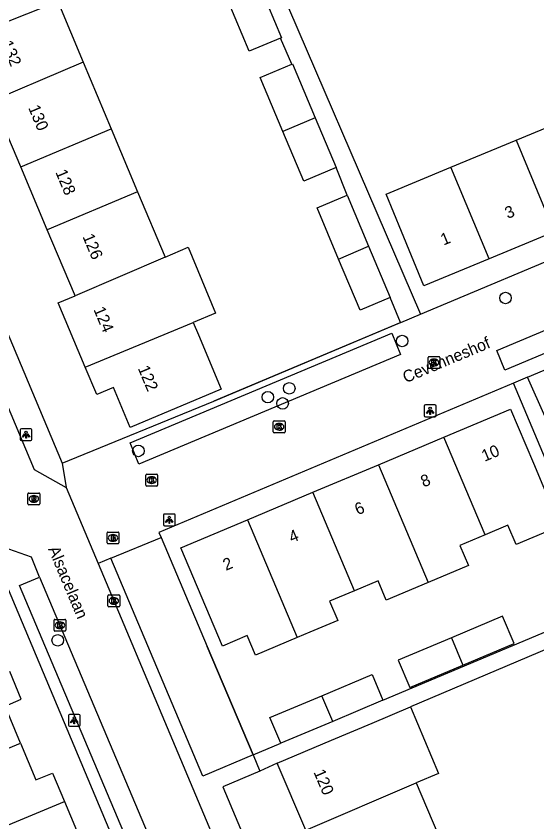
# Model space of a CAD drawing. Extents: x 157767 to 159171, y 387842 to 389425.
# Drawn here: x 158840.3 to 158884.5, y 388397.2 to 388465.6 of the extents above; entities that cross this region are included whole.
import ezdxf

# ---------------------------------------------------------------- set-up
doc = ezdxf.new("R2010")
doc.units = 0
for name, color, linetype in [('IMGEO_Boom', 7, 'Continuous'), ('IMGEO_Brandkraan', 7, 'Continuous'), ('IMGEO_Kolk', 7, 'Continuous'), ('IMGEO_Lichtpunt', 7, 'Continuous'), ('IMGEO_Muur', 7, 'Continuous'), ('IMGEO_Openbare_ruimte_label', 7, 'Continuous'), ('IMGEO_Pand', 7, 'Continuous'), ('IMGEO_Pand_nummerreeks', 7, 'Continuous'), ('IMGEO_Parkeervlak_open', 7, 'Continuous'), ('IMGEO_Rijbaan_lokaal_open', 7, 'Continuous'), ('IMGEO_Rioolput', 7, 'Continuous'), ('IMGEO_Voetpad_open', 7, 'Continuous')]:
    doc.layers.add(name, color=color, linetype=linetype)

msp = doc.modelspace()

# ---------------------------------------------------------------- linework, layer by layer
at = {"layer": 'IMGEO_Boom'}
for centre in [(158881.81, 388441.636), (158873.055, 388437.985), (158863.477, 388433.968), (158861.666, 388433.215), (158862.916, 388432.688), (158850.682, 388428.657), (158843.844, 388412.584)]:
    msp.add_circle(centre, 0.489, dxfattribs=at)
at = {"layer": 'IMGEO_Brandkraan'}
for p, q in [((158848.031, 388420.845), (158848.031, 388421.697)), ((158848.106, 388421.771), (158848.958, 388421.771)), ((158849.032, 388421.697), (158849.032, 388420.845)), ((158848.542, 388420.991), (158848.517, 388420.991)), ((158848.519, 388421.551), (158848.544, 388421.551)), ((158848.958, 388420.771), (158848.106, 388420.771))]:
    msp.add_line(p, q, dxfattribs=at)
for points in [[(158848.031, 388420.845), (158848.031, 388421.697)], [(158848.106, 388421.771), (158848.958, 388421.771)], [(158849.032, 388421.697), (158849.032, 388420.845)], [(158848.379, 388421.471), (158848.379, 388421.071), (158848.592, 388421.071)], [(158848.61, 388421.471), (158848.379, 388421.471)], [(158848.558, 388421.39), (158848.504, 388421.39), (158848.504, 388421.314)], [(158848.504, 388421.314), (158848.557, 388421.314)], [(158848.566, 388421.238), (158848.504, 388421.238), (158848.504, 388421.157)], [(158848.504, 388421.157), (158848.566, 388421.157)], [(158848.958, 388420.771), (158848.106, 388420.771)]]:
    msp.add_lwpolyline(points, dxfattribs=at)
for centre, radius, start, end in [((158848.108, 388421.695), 0.0765, 91.55205, 178.44795), ((158848.108, 388421.695), 0.0765, 91.55205, 178.44795), ((158848.956, 388421.695), 0.0765, 1.55205, 88.44795), ((158848.956, 388421.695), 0.0765, 1.55205, 88.44795), ((158848.559, 388421.352), 0.0379, 267.82845, 90.93552), ((158848.567, 388421.197), 0.0404, 269.87594, 90.50774), ((158848.598, 388421.322), 0.251, 268.66757, 293.53466), ((158848.614, 388421.326), 0.145, 59.4692, 91.53667), ((158848.639, 388421.373), 0.0922, 285.51372, 58.15012), ((158848.644, 388421.181), 0.105, 301.31148, 78.98903), ((158848.108, 388420.847), 0.0765, 181.55205, 268.44795), ((158848.108, 388420.847), 0.0765, 181.55205, 268.44795), ((158848.956, 388420.847), 0.0765, 271.55205, 358.44795), ((158848.956, 388420.847), 0.0765, 271.55205, 358.44795)]:
    msp.add_arc(centre, radius, start, end, dxfattribs=at)
for centre, major_axis, ratio, start_param, end_param in [((158848.518, 388421.271), (-0.387, 0.002), 0.722429, 4.712389, 7.853982), ((158848.543, 388421.271), (-0.39, 0.002), 0.717154, 1.570796, 4.712389)]:
    msp.add_ellipse(centre, major_axis=major_axis, ratio=ratio, start_param=start_param, end_param=end_param, dxfattribs=at)
at = {"layer": 'IMGEO_Kolk'}
for p, q in [((158875.25, 388435.735), (158875.25, 388436.587)), ((158875.325, 388436.661), (158876.177, 388436.661)), ((158875.738, 388436.441), (158875.763, 388436.441)), ((158876.251, 388436.587), (158876.251, 388435.735)), ((158876.177, 388435.661), (158875.325, 388435.661)), ((158875.761, 388435.881), (158875.736, 388435.881)), ((158862.123, 388430.277), (158862.123, 388431.129)), ((158862.198, 388431.203), (158863.05, 388431.203)), ((158862.611, 388430.983), (158862.636, 388430.983)), ((158863.124, 388431.129), (158863.124, 388430.277)), ((158863.05, 388430.203), (158862.198, 388430.203)), ((158862.634, 388430.423), (158862.609, 388430.423)), ((158851.312, 388425.752), (158851.312, 388426.604)), ((158851.387, 388426.678), (158852.239, 388426.678)), ((158851.8, 388426.458), (158851.825, 388426.458)), ((158852.313, 388426.604), (158852.313, 388425.752)), ((158851.823, 388425.898), (158851.798, 388425.898)), ((158852.239, 388425.678), (158851.387, 388425.678)), ((158848.099, 388415.508), (158848.099, 388416.36)), ((158848.174, 388416.434), (158849.026, 388416.434)), ((158848.587, 388416.214), (158848.612, 388416.214)), ((158849.1, 388416.36), (158849.1, 388415.508)), ((158848.61, 388415.654), (158848.585, 388415.654)), ((158849.026, 388415.434), (158848.174, 388415.434)), ((158843.532, 388413.437), (158843.532, 388414.289)), ((158843.607, 388414.363), (158844.459, 388414.363)), ((158844.02, 388414.143), (158844.045, 388414.143)), ((158844.533, 388414.289), (158844.533, 388413.437)), ((158844.043, 388413.583), (158844.018, 388413.583)), ((158844.459, 388413.363), (158843.607, 388413.363))]:
    msp.add_line(p, q, dxfattribs=at)
for points in [[(158875.25, 388435.735), (158875.25, 388436.587)], [(158875.325, 388436.661), (158876.177, 388436.661)], [(158875.571, 388436.361), (158875.694, 388436.361), (158875.694, 388436.21), (158875.824, 388436.361), (158875.988, 388436.361), (158875.842, 388436.21), (158875.995, 388435.961), (158875.843, 388435.961), (158875.758, 388436.125), (158875.694, 388436.058), (158875.694, 388435.961), (158875.571, 388435.961), (158875.571, 388436.361)], [(158876.251, 388436.587), (158876.251, 388435.735)], [(158876.177, 388435.661), (158875.325, 388435.661)], [(158862.123, 388430.277), (158862.123, 388431.129)], [(158862.198, 388431.203), (158863.05, 388431.203)], [(158862.444, 388430.903), (158862.567, 388430.903), (158862.567, 388430.752), (158862.697, 388430.903), (158862.861, 388430.903), (158862.715, 388430.752), (158862.868, 388430.503), (158862.716, 388430.503), (158862.631, 388430.667), (158862.567, 388430.6), (158862.567, 388430.503), (158862.444, 388430.503), (158862.444, 388430.903)], [(158863.124, 388431.129), (158863.124, 388430.277)], [(158863.05, 388430.203), (158862.198, 388430.203)], [(158851.312, 388425.752), (158851.312, 388426.604)], [(158851.387, 388426.678), (158852.239, 388426.678)], [(158852.313, 388426.604), (158852.313, 388425.752)], [(158851.633, 388426.378), (158851.756, 388426.378), (158851.756, 388426.227), (158851.886, 388426.378), (158852.05, 388426.378), (158851.904, 388426.227), (158852.057, 388425.978), (158851.905, 388425.978), (158851.82, 388426.142), (158851.756, 388426.075), (158851.756, 388425.978), (158851.633, 388425.978), (158851.633, 388426.378)], [(158852.239, 388425.678), (158851.387, 388425.678)], [(158848.099, 388415.508), (158848.099, 388416.36)], [(158848.174, 388416.434), (158849.026, 388416.434)], [(158849.1, 388416.36), (158849.1, 388415.508)], [(158848.42, 388416.134), (158848.543, 388416.134), (158848.543, 388415.983), (158848.673, 388416.134), (158848.837, 388416.134), (158848.691, 388415.983), (158848.844, 388415.734), (158848.692, 388415.734), (158848.607, 388415.898), (158848.543, 388415.831), (158848.543, 388415.734), (158848.42, 388415.734), (158848.42, 388416.134)], [(158849.026, 388415.434), (158848.174, 388415.434)], [(158843.532, 388413.437), (158843.532, 388414.289)], [(158843.607, 388414.363), (158844.459, 388414.363)], [(158844.533, 388414.289), (158844.533, 388413.437)], [(158843.853, 388414.063), (158843.976, 388414.063), (158843.976, 388413.912), (158844.106, 388414.063), (158844.27, 388414.063), (158844.124, 388413.912), (158844.277, 388413.663), (158844.125, 388413.663), (158844.04, 388413.827), (158843.976, 388413.76), (158843.976, 388413.663), (158843.853, 388413.663), (158843.853, 388414.063)], [(158844.459, 388413.363), (158843.607, 388413.363)]]:
    msp.add_lwpolyline(points, dxfattribs=at)
for centre, start, end in [((158875.327, 388436.585), 91.55205, 178.44795), ((158875.327, 388436.585), 91.55205, 178.44795), ((158876.175, 388436.585), 1.55205, 88.44795), ((158876.175, 388436.585), 1.55205, 88.44795), ((158875.327, 388435.737), 181.55205, 268.44795), ((158875.327, 388435.737), 181.55205, 268.44795), ((158876.175, 388435.737), 271.55205, 358.44795), ((158876.175, 388435.737), 271.55205, 358.44795), ((158862.2, 388431.127), 91.55205, 178.44795), ((158862.2, 388431.127), 91.55205, 178.44795), ((158863.048, 388431.127), 1.55205, 88.44795), ((158863.048, 388431.127), 1.55205, 88.44795), ((158862.2, 388430.279), 181.55205, 268.44795), ((158862.2, 388430.279), 181.55205, 268.44795), ((158863.048, 388430.279), 271.55205, 358.44795), ((158863.048, 388430.279), 271.55205, 358.44795), ((158851.389, 388426.602), 91.55205, 178.44795), ((158851.389, 388426.602), 91.55205, 178.44795), ((158852.237, 388426.602), 1.55205, 88.44795), ((158852.237, 388426.602), 1.55205, 88.44795), ((158851.389, 388425.754), 181.55205, 268.44795), ((158851.389, 388425.754), 181.55205, 268.44795), ((158852.237, 388425.754), 271.55205, 358.44795), ((158852.237, 388425.754), 271.55205, 358.44795), ((158848.176, 388416.358), 91.55205, 178.44795), ((158848.176, 388416.358), 91.55205, 178.44795), ((158849.024, 388416.358), 1.55205, 88.44795), ((158849.024, 388416.358), 1.55205, 88.44795), ((158848.176, 388415.51), 181.55205, 268.44795), ((158848.176, 388415.51), 181.55205, 268.44795), ((158849.024, 388415.51), 271.55205, 358.44795), ((158849.024, 388415.51), 271.55205, 358.44795), ((158843.609, 388414.287), 91.55205, 178.44795), ((158843.609, 388414.287), 91.55205, 178.44795), ((158844.457, 388414.287), 1.55205, 88.44795), ((158844.457, 388414.287), 1.55205, 88.44795), ((158843.609, 388413.439), 181.55205, 268.44795), ((158843.609, 388413.439), 181.55205, 268.44795), ((158844.457, 388413.439), 271.55205, 358.44795), ((158844.457, 388413.439), 271.55205, 358.44795)]:
    msp.add_arc(centre, 0.0765, start, end, dxfattribs=at)
for centre, major_axis, ratio, start_param, end_param in [((158875.737, 388436.161), (-0.387, 0.002), 0.722429, 4.712389, 7.853982), ((158875.762, 388436.161), (-0.39, 0.002), 0.717154, 1.570796, 4.712389), ((158862.61, 388430.703), (-0.387, 0.002), 0.722429, 4.712389, 7.853982), ((158862.635, 388430.703), (-0.39, 0.002), 0.717154, 1.570796, 4.712389), ((158851.799, 388426.178), (-0.387, 0.002), 0.722429, 4.712389, 7.853982), ((158851.824, 388426.178), (-0.39, 0.002), 0.717154, 1.570796, 4.712389), ((158848.586, 388415.934), (-0.387, 0.002), 0.722429, 4.712389, 7.853982), ((158848.611, 388415.934), (-0.39, 0.002), 0.717154, 1.570796, 4.712389), ((158844.019, 388413.863), (-0.387, 0.002), 0.722429, 4.712389, 7.853982), ((158844.044, 388413.863), (-0.39, 0.002), 0.717154, 1.570796, 4.712389)]:
    msp.add_ellipse(centre, major_axis=major_axis, ratio=ratio, start_param=start_param, end_param=end_param, dxfattribs=at)
at = {"layer": 'IMGEO_Lichtpunt'}
for p, q in [((158874.926, 388432.461), (158874.926, 388431.654)), ((158874.926, 388432.461), (158874.926, 388431.654)), ((158875.828, 388432.556), (158875.02, 388432.556)), ((158875.828, 388432.556), (158875.02, 388432.556)), ((158875.922, 388431.654), (158875.922, 388432.461)), ((158875.922, 388431.654), (158875.922, 388432.461)), ((158875.02, 388431.56), (158875.828, 388431.56)), ((158875.02, 388431.56), (158875.828, 388431.56)), ((158840.665, 388430.439), (158840.665, 388429.632)), ((158840.665, 388430.439), (158840.665, 388429.632)), ((158841.567, 388430.534), (158840.759, 388430.534)), ((158841.567, 388430.534), (158840.759, 388430.534)), ((158841.661, 388429.632), (158841.661, 388430.439)), ((158841.661, 388429.632), (158841.661, 388430.439)), ((158840.759, 388429.538), (158841.567, 388429.538)), ((158840.759, 388429.538), (158841.567, 388429.538)), ((158852.807, 388423.209), (158852.807, 388422.402)), ((158852.807, 388423.209), (158852.807, 388422.402)), ((158853.709, 388423.304), (158852.901, 388423.304)), ((158853.709, 388423.304), (158852.901, 388423.304)), ((158853.803, 388422.402), (158853.803, 388423.209)), ((158853.803, 388422.402), (158853.803, 388423.209)), ((158852.901, 388422.308), (158853.709, 388422.308)), ((158852.901, 388422.308), (158853.709, 388422.308)), ((158844.746, 388406.2), (158844.746, 388405.393)), ((158844.746, 388406.2), (158844.746, 388405.393)), ((158845.648, 388406.295), (158844.84, 388406.295)), ((158845.648, 388406.295), (158844.84, 388406.295)), ((158845.742, 388405.393), (158845.742, 388406.2)), ((158845.742, 388405.393), (158845.742, 388406.2)), ((158844.84, 388405.299), (158845.648, 388405.299)), ((158844.84, 388405.299), (158845.648, 388405.299))]:
    msp.add_line(p, q, dxfattribs=at)
for points in [[(158875.3, 388432.125), (158875.339, 388432.097), (158875.151, 388431.835), (158875.113, 388431.862), (158875.3, 388432.125)], [(158875.402, 388432.077), (158875.449, 388432.077), (158875.449, 388431.755), (158875.402, 388431.755), (158875.402, 388432.077)], [(158875.512, 388432.097), (158875.55, 388432.124), (158875.737, 388431.862), (158875.698, 388431.834), (158875.512, 388432.097)], [(158841.039, 388430.103), (158841.078, 388430.075), (158840.89, 388429.813), (158840.852, 388429.84), (158841.039, 388430.103)], [(158841.141, 388430.055), (158841.188, 388430.055), (158841.188, 388429.733), (158841.141, 388429.733), (158841.141, 388430.055)], [(158841.251, 388430.075), (158841.289, 388430.102), (158841.476, 388429.84), (158841.437, 388429.812), (158841.251, 388430.075)], [(158853.181, 388422.873), (158853.22, 388422.845), (158853.032, 388422.583), (158852.994, 388422.61), (158853.181, 388422.873)], [(158853.283, 388422.825), (158853.33, 388422.825), (158853.33, 388422.503), (158853.283, 388422.503), (158853.283, 388422.825)], [(158853.393, 388422.845), (158853.431, 388422.872), (158853.618, 388422.61), (158853.579, 388422.582), (158853.393, 388422.845)], [(158845.12, 388405.864), (158845.159, 388405.836), (158844.971, 388405.574), (158844.933, 388405.601), (158845.12, 388405.864)], [(158845.222, 388405.816), (158845.269, 388405.816), (158845.269, 388405.494), (158845.222, 388405.494), (158845.222, 388405.816)], [(158845.332, 388405.836), (158845.37, 388405.863), (158845.557, 388405.601), (158845.518, 388405.573), (158845.332, 388405.836)]]:
    msp.add_lwpolyline(points, dxfattribs=at)
for centre in [(158875.425, 388432.259), (158841.164, 388430.237), (158853.306, 388423.007), (158845.245, 388405.998)]:
    msp.add_circle(centre, 0.0994, dxfattribs=at)
for centre, start, end in [((158875.02, 388432.461), 90, 180), ((158875.02, 388432.461), 90, 180), ((158875.828, 388432.461), 0, 90), ((158875.828, 388432.461), 0, 90), ((158875.02, 388431.654), 180, 270), ((158875.02, 388431.654), 180, 270), ((158875.828, 388431.654), 270, 0), ((158875.828, 388431.654), 270, 360), ((158840.759, 388430.439), 90, 180), ((158840.759, 388430.439), 90, 180), ((158841.567, 388430.439), 0, 90), ((158841.567, 388430.439), 0, 90), ((158840.759, 388429.632), 180, 270), ((158840.759, 388429.632), 180, 270), ((158841.567, 388429.632), 270, 0), ((158841.567, 388429.632), 270, 360), ((158852.901, 388423.209), 90, 180), ((158852.901, 388423.209), 90, 180), ((158853.709, 388423.209), 0, 90), ((158853.709, 388423.209), 0, 90), ((158852.901, 388422.402), 180, 270), ((158852.901, 388422.402), 180, 270), ((158853.709, 388422.402), 270, 0), ((158853.709, 388422.402), 270, 360), ((158844.84, 388406.2), 90, 180), ((158844.84, 388406.2), 90, 180), ((158845.648, 388406.2), 0, 90), ((158845.648, 388406.2), 0, 90), ((158844.84, 388405.393), 180, 270), ((158844.84, 388405.393), 180, 270), ((158845.648, 388405.393), 270, 0), ((158845.648, 388405.393), 270, 360)]:
    msp.add_arc(centre, 0.0946, start, end, dxfattribs=at)
at = {"layer": 'IMGEO_Muur'}
for points in [[(158872.931, 388439.569), (158857.081, 388432.872)], [(158860.405, 388402.853), (158856.513, 388412.065)]]:
    msp.add_lwpolyline(points, dxfattribs=at)
at = {"layer": 'IMGEO_Pand'}
for points in [[(158861.041, 388467.989), (158862.83, 388463.725), (158862.746, 388463.69)], [(158836.088, 388463.7), (158843.849, 388466.784)], [(158843.849, 388466.784), (158846.008, 388461.637)], [(158862.746, 388463.69), (158860.086, 388462.573), (158858.298, 388466.836)], [(158846.008, 388461.637), (158836.952, 388457.813)], [(158846.008, 388461.637), (158848.377, 388455.994)], [(158862.94, 388455.77), (158861.016, 388460.357), (158863.683, 388461.476)], [(158863.683, 388461.476), (158863.76, 388461.508), (158865.683, 388456.924)], [(158840.716, 388452.779), (158839.316, 388456.114), (158837.913, 388455.525), (158836.952, 388457.813)], [(158882.718, 388455.018), (158888.245, 388457.311)], [(158865.683, 388456.924), (158862.94, 388455.77)], [(158865.683, 388456.924), (158867.453, 388452.704)], [(158840.716, 388452.779), (158848.377, 388455.994)], [(158848.377, 388455.994), (158850.623, 388450.64)], [(158867.453, 388452.704), (158864.709, 388451.553), (158862.94, 388455.77)], [(158877.192, 388452.726), (158882.718, 388455.018)], [(158882.718, 388455.018), (158885.944, 388447.243)], [(158842.963, 388447.425), (158840.716, 388452.779)], [(158880.418, 388444.951), (158874.892, 388442.658), (158873.001, 388447.274), (158871.687, 388450.442), (158877.192, 388452.726)], [(158880.418, 388444.951), (158877.192, 388452.726)], [(158850.623, 388450.64), (158842.963, 388447.425)], [(158850.623, 388450.64), (158852.948, 388445.102)], [(158867.66, 388444.937), (158865.832, 388449.292), (158868.388, 388450.365)], [(158868.388, 388450.365), (158870.201, 388446.044)], [(158845.31, 388441.83), (158845.258, 388441.955), (158842.963, 388447.425)], [(158885.944, 388447.243), (158880.418, 388444.951)], [(158852.948, 388445.102), (158854.913, 388445.949), (158857.229, 388440.35), (158855.329, 388439.564)], [(158867.66, 388444.937), (158870.201, 388446.044)], [(158870.201, 388446.044), (158872.039, 388441.665)], [(158852.948, 388445.102), (158845.31, 388441.83)], [(158872.039, 388441.665), (158869.483, 388440.592), (158867.66, 388444.937)], [(158846.177, 388435.778), (158843.892, 388441.222), (158845.31, 388441.83)], [(158855.329, 388439.564), (158855.776, 388438.498), (158857.711, 388433.887), (158849.996, 388430.649), (158848.573, 388434.041), (158847.155, 388433.446), (158846.177, 388435.778)], [(158846.177, 388435.778), (158855.329, 388439.564)], [(158876.577, 388429.828), (158882.232, 388432.213), (158884.175, 388427.607), (158886.426, 388422.272), (158882.706, 388420.702), (158882.014, 388422.343), (158880.079, 388421.526)], [(158871.033, 388427.489), (158876.577, 388429.828)], [(158880.079, 388421.526), (158876.577, 388429.828)], [(158865.488, 388425.15), (158871.033, 388427.489)], [(158871.033, 388427.489), (158875.251, 388417.488)], [(158859.944, 388422.811), (158865.488, 388425.15)], [(158869.015, 388416.793), (158865.488, 388425.15)], [(158864.155, 388412.832), (158860.612, 388411.338), (158859.918, 388412.983), (158857.805, 388412.091), (158854.289, 388420.426), (158859.944, 388422.811)], [(158859.944, 388422.811), (158864.155, 388412.832)], [(158880.079, 388421.526), (158877.952, 388420.629), (158878.669, 388418.93), (158875.251, 388417.488)], [(158875.251, 388417.488), (158871.708, 388415.994), (158871.015, 388417.636), (158869.015, 388416.793)], [(158869.015, 388416.793), (158866.9, 388415.901), (158867.584, 388414.279), (158865.219, 388413.281), (158864.155, 388412.832)], [(158878.205, 388410.484), (158882.539, 388412.313), (158881.558, 388414.637), (158877.225, 388412.808)], [(158877.225, 388412.808), (158872.714, 388410.905), (158873.694, 388408.58), (158878.205, 388410.484)], [(158877.225, 388412.808), (158878.205, 388410.484)], [(158840.69, 388403.87), (158839.385, 388407.006), (158840.758, 388407.578), (158839.776, 388409.938)], [(158866.242, 388407.883), (158870.494, 388409.677), (158871.414, 388407.497)], [(158862.751, 388403.843), (158861.832, 388406.022), (158866.242, 388407.883)], [(158867.162, 388405.703), (158866.242, 388407.883)], [(158871.414, 388407.497), (158867.162, 388405.703)], [(158862.463, 388402.156), (158867.068, 388404.105), (158870.512, 388405.562), (158873.745, 388406.93)], [(158873.745, 388406.93), (158876.138, 388401.276), (158874.252, 388400.478)], [(158867.162, 388405.703), (158862.751, 388403.843)], [(158832.917, 388400.635), (158840.69, 388403.87)], [(158840.69, 388403.87), (158841.995, 388400.735), (158843.409, 388401.323), (158844.419, 388398.895)], [(158864.872, 388396.463), (158862.463, 388402.156)], [(158864.872, 388396.463), (158874.252, 388400.478)], [(158874.252, 388400.478), (158876.559, 388395.026)], [(158835.23, 388395.077), (158844.419, 388398.895)], [(158844.419, 388398.895), (158845.43, 388396.466), (158844.131, 388395.925), (158845.438, 388392.785)]]:
    msp.add_lwpolyline(points, dxfattribs=at)
at = {"layer": 'IMGEO_Parkeervlak_open'}
msp.add_lwpolyline([(158852.611, 388421.301), (158856.513, 388412.065), (158860.405, 388402.853)], dxfattribs=at)
at = {"layer": 'IMGEO_Rijbaan_lokaal_open'}
for points in [[(158833.318, 388447.382), (158841.848, 388427.082), (158842.299, 388426.827), (158844.547, 388425.555)], [(158842.313, 388417.957), (158841.608, 388419.637), (158839.22, 388420.499), (158836.188, 388427.662)], [(158844.547, 388425.555), (158847.266, 388419.093)], [(158847.266, 388419.093), (158859.88, 388389.119)], [(158842.313, 388417.957), (158855.282, 388387.184)]]:
    msp.add_lwpolyline(points, dxfattribs=at)
at = {"layer": 'IMGEO_Rioolput'}
for p, q in [((158841.397, 388425.081), (158842.249, 388425.081)), ((158841.322, 388424.155), (158841.322, 388425.007)), ((158841.81, 388424.861), (158841.835, 388424.861)), ((158842.323, 388425.007), (158842.323, 388424.155)), ((158842.249, 388424.081), (158841.397, 388424.081)), ((158841.833, 388424.301), (158841.808, 388424.301))]:
    msp.add_line(p, q, dxfattribs=at)
for points in [[(158841.397, 388425.081), (158842.249, 388425.081)], [(158841.322, 388424.155), (158841.322, 388425.007)], [(158841.911, 388424.779), (158841.659, 388424.781), (158841.659, 388424.381)], [(158841.659, 388424.381), (158841.783, 388424.381), (158841.783, 388424.543), (158841.794, 388424.543)], [(158841.837, 388424.7), (158841.783, 388424.7), (158841.783, 388424.619)], [(158841.783, 388424.619), (158841.835, 388424.619)], [(158841.841, 388424.514), (158841.912, 388424.381), (158842.052, 388424.381), (158841.987, 388424.507)], [(158842.323, 388425.007), (158842.323, 388424.155)], [(158842.249, 388424.081), (158841.397, 388424.081)]]:
    msp.add_lwpolyline(points, dxfattribs=at)
for centre, radius, start, end in [((158841.399, 388425.005), 0.0765, 91.55205, 178.44795), ((158841.399, 388425.005), 0.0765, 91.55205, 178.44795), ((158842.247, 388425.005), 0.0765, 1.55205, 88.44795), ((158842.247, 388425.005), 0.0765, 1.55205, 88.44795), ((158841.793, 388424.49), 0.0533, 26.02933, 88.69889), ((158841.819, 388424.808), 0.19, 274.7715, 282.96867), ((158841.843, 388424.604), 0.0964, 77.00612, 93.18647), ((158841.857, 388424.661), 0.0378, 276.66336, 79.67722), ((158841.91, 388424.669), 0.109, 350.36119, 89.41601), ((158841.908, 388424.669), 0.112, 277.58423, 350.98172), ((158841.892, 388424.454), 0.108, 29.51342, 73.79051), ((158841.399, 388424.157), 0.0765, 181.55205, 268.44795), ((158841.399, 388424.157), 0.0765, 181.55205, 268.44795), ((158842.247, 388424.157), 0.0765, 271.55205, 358.44795), ((158842.247, 388424.157), 0.0765, 271.55205, 358.44795)]:
    msp.add_arc(centre, radius, start, end, dxfattribs=at)
for centre, major_axis, ratio, start_param, end_param in [((158841.809, 388424.581), (-0.387, 0.002), 0.722429, 4.712389, 7.853982), ((158841.834, 388424.581), (-0.39, 0.002), 0.717154, 1.570796, 4.712389)]:
    msp.add_ellipse(centre, major_axis=major_axis, ratio=ratio, start_param=start_param, end_param=end_param, dxfattribs=at)
at = {"layer": 'IMGEO_Voetpad_open'}
for points in [[(158817.645, 388490.937), (158844.215, 388427.61)], [(158883.151, 388482.312), (158883.12, 388482.376), (158860.503, 388473.046), (158874.609, 388440.274)], [(158863.683, 388461.476), (158862.746, 388463.69)], [(158874.609, 388440.274), (158903.16, 388452.266), (158904.198, 388455.161)], [(158868.388, 388450.365), (158867.453, 388452.704)], [(158881.068, 388437.17), (158905.163, 388447.292), (158905.862, 388445.627), (158881.767, 388435.505), (158881.068, 388437.17)], [(158883.689, 388434.919), (158906.396, 388444.484), (158909.047, 388443.375)], [(158872.921, 388439.565), (158872.039, 388441.665)], [(158872.921, 388439.565), (158872.931, 388439.569), (158874.609, 388440.274)], [(158844.215, 388427.61), (158857.081, 388432.872), (158872.921, 388439.565)], [(158850.726, 388427.527), (158849.979, 388429.333), (158872.164, 388438.653), (158872.921, 388436.852), (158850.726, 388427.527)], [(158883.689, 388434.919), (158882.487, 388434.413)], [(158896.145, 388406.125), (158892.217, 388415.61), (158886.775, 388427.932), (158883.689, 388434.919)], [(158882.487, 388434.413), (158852.422, 388421.748), (158852.611, 388421.301)], [(158889.429, 388417.934), (158882.487, 388434.413)], [(158844.215, 388427.61), (158844.547, 388425.555)], [(158848.355, 388419.543), (158852.611, 388421.301)], [(158838.652, 388419.211), (158868.881, 388347.284), (158853.592, 388340.805), (158843.883, 388336.691), (158834.401, 388332.713), (158827.967, 388330.084)], [(158848.355, 388419.543), (158847.266, 388419.093)], [(158860.405, 388402.853), (158856.162, 388401.064), (158848.355, 388419.543)], [(158870.521, 388351.022), (158868.839, 388350.328), (158840.615, 388417.244), (158842.313, 388417.957)], [(158871.414, 388407.497), (158890.448, 388415.515), (158890.416, 388415.59)], [(158888.296, 388413.111), (158873.745, 388406.93)], [(158860.405, 388402.853), (158862.751, 388403.843)], [(158860.405, 388402.853), (158860.985, 388401.48)], [(158862.463, 388402.156), (158860.985, 388401.48)], [(158860.985, 388401.48), (158857.849, 388400.164), (158869.979, 388371.299), (158870.387, 388370.328)]]:
    msp.add_lwpolyline(points, dxfattribs=at)

# ---------------------------------------------------------------- texts
at = {"layer": 'IMGEO_Openbare_ruimte_label'}
for s, rotation, p in [('Cevenneshof', 22.76973, (158873.352, 388434.398)), ('Alsacelaan', 292.76973, (158843.014, 388420.338))]:
    msp.add_text(s, height=1, rotation=rotation, dxfattribs=at).set_placement(p)
at = {"layer": 'IMGEO_Pand_nummerreeks'}
for s, rotation, p in [('132', 292.8449, (158839.022, 388463.25)), ('130', 292.8449, (158841.327, 388457.779)), ('128', 292.8449, (158843.629, 388452.314)), ('3', 22.53393, (158882.004, 388448.336)), ('126', 292.84362, (158845.929, 388446.852)), ('1', 22.53393, (158876.555, 388446.076)), ('124', 292.7634, (158846.86, 388440.662)), ('122', 292.75885, (158850.621, 388435.671)), ('10', 22.87113, (158880.038, 388427.728)), ('8', 22.87113, (158874.874, 388425.549)), ('6', 22.87113, (158869.282, 388423.19)), ('4', 22.87113, (158863.693, 388420.833)), ('2', 22.87113, (158858.103, 388418.475)), ('120', 292.93242, (158865.517, 388401.403))]:
    msp.add_text(s, height=1, rotation=rotation, dxfattribs=at).set_placement(p)

doc.saveas('drawing.dxf')
